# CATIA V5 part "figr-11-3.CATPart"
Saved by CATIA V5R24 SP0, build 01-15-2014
Part number: Part1
Bounding box of the stored display mesh (mm): x -50 to 50, y -98.731 to 72.975, z 0 to 120
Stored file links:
  D:\KAVITA\CATIA V5-6R2014 Project_ Kavita\CATIA V5-6R2014_partfiles\Partfiles\c11_catia_v5-6r2014_prt\figr-11-3.CATPart
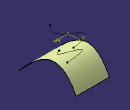
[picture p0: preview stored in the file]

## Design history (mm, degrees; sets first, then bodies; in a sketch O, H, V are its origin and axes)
Set1
  Sketch1 on yz-plane, origin (0, 0, 0), H (0, 1, 0), V (0, 0, 1)
    spline S1 through (-98.7309, 0) (-73.2816, 27.1192) (0, 74.8227) (72.975, 18.624)
    point P1 (-98.7309, 0)
    point P2 (0, 74.8227)
    coincidence: P1 H, P2 V
  Extrude1: Element1 Sketch1, Lim1 50, Lim2 50, Direction yz-plane
  Plane1: type Offset, RefPlane xy-plane, Offset 120
  Sketch2 on Plane1, origin (0, 0, 120), H (1, 0, 0), V (0, 1, 0)
    spline S1 through (28.7787, 44.6229) (-22.3035, 19.7059) (20.5049, -22.8447) (5.396, -48.9118)
  Project1: ToProject Sketch2, Support Extrude1
Body1 (main body)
